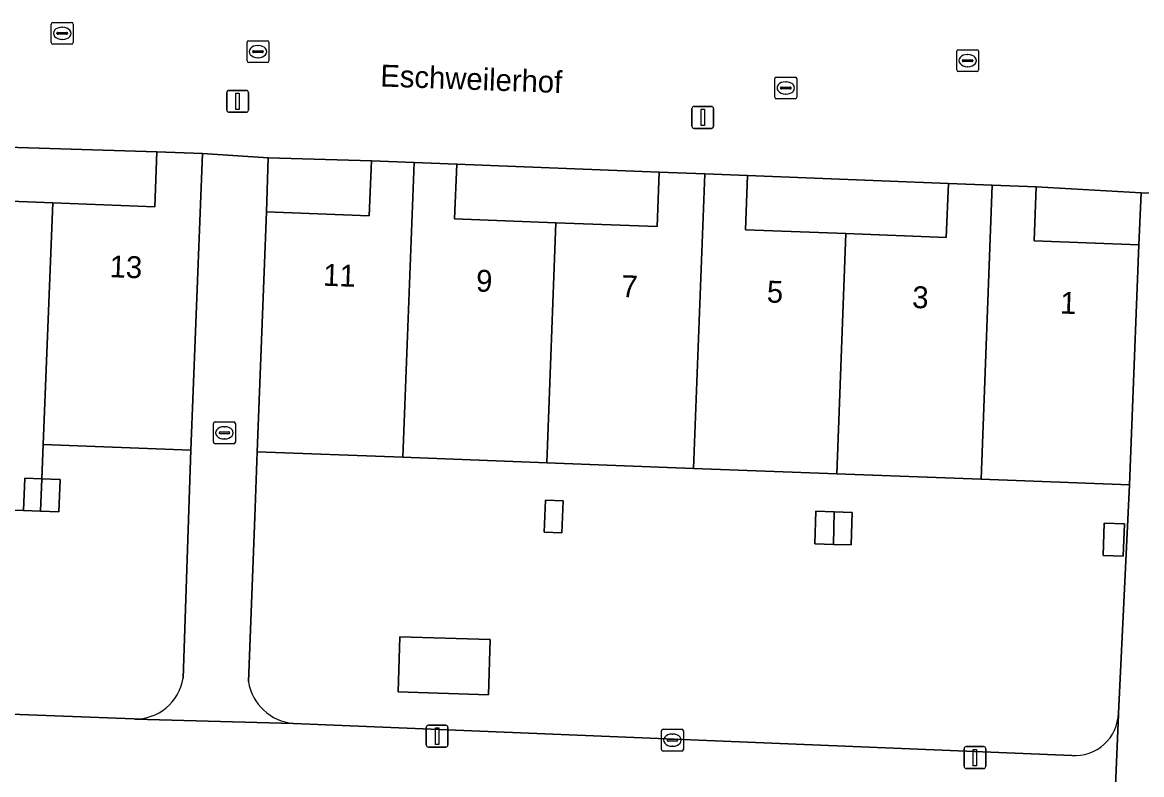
# Model space of a CAD drawing. Extents: x 160786 to 161429, y 386828 to 387485.
# Drawn here: x 161232.7 to 161283.9, y 387067.7 to 387102.1 of the extents above; entities that cross this region are included whole.
import ezdxf

# ---------------------------------------------------------------- set-up
doc = ezdxf.new("R2010")
doc.units = 0
for name, color, linetype in [('IMGEO_Erf', 7, 'Continuous'), ('IMGEO_Kolk', 7, 'Continuous'), ('IMGEO_Lichtmast', 7, 'Continuous'), ('IMGEO_Muur', 7, 'Continuous'), ('IMGEO_Openbare_ruimte_label', 7, 'Continuous'), ('IMGEO_Pand', 7, 'Continuous'), ('IMGEO_Pand_nummerreeks', 7, 'Continuous'), ('IMGEO_Rijbaan_lokaal_open', 7, 'Continuous'), ('IMGEO_Rioolput', 7, 'Continuous'), ('IMGEO_Voetpad_open', 7, 'Continuous')]:
    doc.layers.add(name, color=color, linetype=linetype)

msp = doc.modelspace()

# ---------------------------------------------------------------- linework, layer by layer
at = {"layer": 'IMGEO_Erf'}
for points in [[(161229.53, 387096.472), (161229.433, 387094.021), (161234.095, 387093.837), (161238.757, 387093.653), (161238.856, 387096.178)], [(161243.95, 387095.898), (161243.869, 387093.434), (161248.578, 387093.255), (161248.673, 387095.761)], [(161252.576, 387095.613), (161252.481, 387093.11), (161257.118, 387092.934), (161261.756, 387092.758), (161261.85, 387095.243)], [(161265.882, 387095.09), (161265.788, 387092.608), (161270.388, 387092.434), (161274.983, 387092.26), (161275.077, 387094.727)], [(161279.094, 387094.575), (161279.001, 387092.11), (161283.788, 387091.928), (161283.907, 387094.295)], [(161256.58, 387078.785), (161256.636, 387080.245), (161257.45, 387080.214), (161257.394, 387078.754)], [(161269.855, 387079.712), (161270.678, 387079.689), (161270.636, 387078.196), (161269.813, 387078.219), (161268.97, 387078.243), (161269.012, 387079.736)], [(161282.156, 387077.722), (161282.212, 387079.197), (161283.13, 387079.163), (161283.074, 387077.687)], [(161254.114, 387073.869), (161254.033, 387071.349), (161249.892, 387071.482), (161249.972, 387074.002)]]:
    msp.add_lwpolyline(points, close=True, dxfattribs=at)
for points in [[(161240.412, 387082.531), (161233.659, 387082.798), (161233.597, 387081.221), (161234.424, 387081.187), (161234.363, 387079.705), (161233.538, 387079.739), (161232.755, 387079.771), (161227.115, 387079.918)], [(161240.055, 387072.111), (161240.412, 387082.531)], [(161283.371, 387080.944), (161276.575, 387081.202), (161269.971, 387081.452), (161263.414, 387081.701), (161256.701, 387081.956), (161250.113, 387082.205), (161243.452, 387082.458), (161243.336, 387079.461), (161243.043, 387071.949)], [(161282.861, 387070.505), (161283.371, 387080.944)], [(161181.932, 387072.363), (161237.801, 387070.245)], [(161245.106, 387070.035), (161280.727, 387068.57)]]:
    msp.add_lwpolyline(points, dxfattribs=at)
for centre, radius, start, end in [((161237.887, 387072.436), 2.192, 267.7549, 351.4852), ((161245.318, 387072.333), 2.307, 189.5681, 264.7232), ((161280.858, 387070.57), 2.004, 266.2516, 358.1486)]:
    msp.add_arc(centre, radius, start, end, dxfattribs=at)
at = {"layer": 'IMGEO_Kolk'}
for p, q in [((161242.982, 387100.332), (161242.982, 387101.184)), ((161243.057, 387101.258), (161243.909, 387101.258)), ((161243.47, 387101.038), (161243.495, 387101.038)), ((161243.983, 387101.184), (161243.983, 387100.332)), ((161243.241, 387100.752), (161243.241, 387100.764)), ((161243.679, 387100.715), (161243.281, 387100.715)), ((161243.284, 387100.801), (161243.682, 387100.801)), ((161243.493, 387100.478), (161243.468, 387100.478)), ((161243.725, 387100.764), (161243.725, 387100.752)), ((161243.909, 387100.258), (161243.057, 387100.258)), ((161267.135, 387098.67), (161267.135, 387099.522)), ((161267.21, 387099.596), (161268.062, 387099.596)), ((161267.623, 387099.376), (161267.648, 387099.376)), ((161268.136, 387099.522), (161268.136, 387098.67)), ((161267.394, 387099.09), (161267.394, 387099.102)), ((161267.832, 387099.053), (161267.434, 387099.053)), ((161267.437, 387099.139), (161267.835, 387099.139)), ((161267.646, 387098.816), (161267.621, 387098.816)), ((161267.878, 387099.102), (161267.878, 387099.09)), ((161268.062, 387098.596), (161267.21, 387098.596)), ((161241.446, 387082.898), (161241.446, 387083.75)), ((161241.521, 387083.824), (161242.373, 387083.824)), ((161241.934, 387083.604), (161241.959, 387083.604)), ((161242.447, 387083.75), (161242.447, 387082.898)), ((161241.705, 387083.318), (161241.705, 387083.33)), ((161242.143, 387083.281), (161241.745, 387083.281)), ((161241.748, 387083.367), (161242.146, 387083.367)), ((161241.957, 387083.044), (161241.932, 387083.044)), ((161242.189, 387083.33), (161242.189, 387083.318)), ((161242.373, 387082.824), (161241.521, 387082.824)), ((161261.948, 387068.846), (161261.948, 387069.698)), ((161262.023, 387069.772), (161262.875, 387069.772)), ((161262.949, 387069.698), (161262.949, 387068.846)), ((161262.207, 387069.266), (161262.207, 387069.278)), ((161262.645, 387069.229), (161262.247, 387069.229)), ((161262.25, 387069.315), (161262.648, 387069.315)), ((161262.436, 387069.552), (161262.461, 387069.552)), ((161262.691, 387069.278), (161262.691, 387069.266)), ((161262.875, 387068.772), (161262.023, 387068.772)), ((161262.459, 387068.992), (161262.434, 387068.992))]:
    msp.add_line(p, q, dxfattribs=at)
for points in [[(161242.982, 387100.332), (161242.982, 387101.184)], [(161243.057, 387101.258), (161243.909, 387101.258)], [(161243.983, 387101.184), (161243.983, 387100.332)], [(161243.909, 387100.258), (161243.057, 387100.258)], [(161267.135, 387098.67), (161267.135, 387099.522)], [(161267.21, 387099.596), (161268.062, 387099.596)], [(161268.136, 387099.522), (161268.136, 387098.67)], [(161268.062, 387098.596), (161267.21, 387098.596)], [(161241.446, 387082.898), (161241.446, 387083.75)], [(161241.521, 387083.824), (161242.373, 387083.824)], [(161242.447, 387083.75), (161242.447, 387082.898)], [(161242.373, 387082.824), (161241.521, 387082.824)], [(161261.948, 387068.846), (161261.948, 387069.698)], [(161262.023, 387069.772), (161262.875, 387069.772)], [(161262.949, 387069.698), (161262.949, 387068.846)], [(161262.875, 387068.772), (161262.023, 387068.772)]]:
    msp.add_lwpolyline(points, dxfattribs=at)
for centre, radius, start, end in [((161243.059, 387101.182), 0.0765, 91.552, 178.448), ((161243.059, 387101.182), 0.0765, 91.552, 178.448), ((161243.907, 387101.182), 0.0765, 1.552, 88.448), ((161243.907, 387101.182), 0.0765, 1.552, 88.448), ((161243.059, 387100.334), 0.0765, 181.552, 268.448), ((161243.059, 387100.334), 0.0765, 181.552, 268.448), ((161243.281, 387100.761), 0.0403, 85.8775, 175.7526), ((161243.278, 387100.751), 0.0366, 178.938, 274.7102), ((161243.682, 387100.758), 0.043, 264.8664, 352.4533), ((161243.686, 387100.763), 0.0386, 1.7309, 96.639), ((161243.907, 387100.334), 0.0765, 271.552, 358.448), ((161243.907, 387100.334), 0.0765, 271.552, 358.448), ((161267.212, 387099.52), 0.0765, 91.552, 178.448), ((161267.212, 387099.52), 0.0765, 91.552, 178.448), ((161268.06, 387099.52), 0.0765, 1.552, 88.448), ((161268.06, 387099.52), 0.0765, 1.552, 88.448), ((161267.434, 387099.099), 0.0403, 85.8775, 175.7526), ((161267.431, 387099.089), 0.0366, 178.938, 274.7102), ((161267.835, 387099.096), 0.043, 264.8664, 352.4533), ((161267.839, 387099.101), 0.0386, 1.7309, 96.639), ((161267.212, 387098.672), 0.0765, 181.552, 268.448), ((161267.212, 387098.672), 0.0765, 181.552, 268.448), ((161268.06, 387098.672), 0.0765, 271.552, 358.448), ((161268.06, 387098.672), 0.0765, 271.552, 358.448), ((161241.523, 387083.748), 0.0765, 91.552, 178.448), ((161241.523, 387083.748), 0.0765, 91.552, 178.448), ((161242.371, 387083.748), 0.0765, 1.552, 88.448), ((161242.371, 387083.748), 0.0765, 1.552, 88.448), ((161241.745, 387083.327), 0.0403, 85.8775, 175.7526), ((161241.742, 387083.317), 0.0366, 178.938, 274.7102), ((161242.146, 387083.324), 0.043, 264.8664, 352.4533), ((161242.15, 387083.329), 0.0386, 1.7309, 96.639), ((161241.523, 387082.9), 0.0765, 181.552, 268.448), ((161241.523, 387082.9), 0.0765, 181.552, 268.448), ((161242.371, 387082.9), 0.0765, 271.552, 358.448), ((161242.371, 387082.9), 0.0765, 271.552, 358.448), ((161262.025, 387069.696), 0.0765, 91.552, 178.448), ((161262.025, 387069.696), 0.0765, 91.552, 178.448), ((161262.873, 387069.696), 0.0765, 1.552, 88.448), ((161262.873, 387069.696), 0.0765, 1.552, 88.448), ((161262.247, 387069.275), 0.0403, 85.8775, 175.7526), ((161262.244, 387069.265), 0.0366, 178.938, 274.7102), ((161262.648, 387069.272), 0.043, 264.8664, 352.4533), ((161262.652, 387069.277), 0.0386, 1.7309, 96.639), ((161262.025, 387068.848), 0.0765, 181.552, 268.448), ((161262.025, 387068.848), 0.0765, 181.552, 268.448), ((161262.873, 387068.848), 0.0765, 271.552, 358.448), ((161262.873, 387068.848), 0.0765, 271.552, 358.448)]:
    msp.add_arc(centre, radius, start, end, dxfattribs=at)
for centre, major_axis, ratio, start_param, end_param in [((161243.469, 387100.758), (-0.387, 0.002), 0.722429, 4.712389, 7.853982), ((161243.494, 387100.758), (-0.39, 0.002), 0.717154, 1.570796, 4.712389), ((161267.622, 387099.096), (-0.387, 0.002), 0.722429, 4.712389, 7.853982), ((161267.647, 387099.096), (-0.39, 0.002), 0.717154, 1.570796, 4.712389), ((161241.933, 387083.324), (-0.387, 0.002), 0.722429, 4.712389, 7.853982), ((161241.958, 387083.324), (-0.39, 0.002), 0.717154, 1.570796, 4.712389), ((161262.435, 387069.272), (-0.387, 0.002), 0.722429, 4.712389, 7.853982), ((161262.46, 387069.272), (-0.39, 0.002), 0.717154, 1.570796, 4.712389)]:
    msp.add_ellipse(centre, major_axis=major_axis, ratio=ratio, start_param=start_param, end_param=end_param, dxfattribs=at)
at = {"layer": 'IMGEO_Lichtmast'}
for p, q in [((161242.054, 387098.087), (161242.054, 387098.887)), ((161242.054, 387098.887), (161242.054, 387098.087)), ((161242.154, 387098.987), (161242.944, 387098.987)), ((161242.944, 387098.987), (161242.154, 387098.987)), ((161243.044, 387098.887), (161243.044, 387098.087)), ((161243.044, 387098.087), (161243.044, 387098.887)), ((161242.944, 387097.987), (161242.154, 387097.987)), ((161242.154, 387097.987), (161242.944, 387097.987)), ((161263.342, 387097.35), (161263.342, 387098.15)), ((161263.342, 387098.15), (161263.342, 387097.35)), ((161263.442, 387098.25), (161264.232, 387098.25)), ((161264.232, 387098.25), (161263.442, 387098.25)), ((161264.332, 387098.15), (161264.332, 387097.35)), ((161264.332, 387097.35), (161264.332, 387098.15)), ((161264.232, 387097.25), (161263.442, 387097.25)), ((161263.442, 387097.25), (161264.232, 387097.25)), ((161251.184, 387069.052), (161251.184, 387069.852)), ((161251.184, 387069.852), (161251.184, 387069.052)), ((161251.284, 387069.952), (161252.074, 387069.952)), ((161252.074, 387069.952), (161251.284, 387069.952)), ((161252.174, 387069.852), (161252.174, 387069.052)), ((161252.174, 387069.052), (161252.174, 387069.852)), ((161252.074, 387068.952), (161251.284, 387068.952)), ((161251.284, 387068.952), (161252.074, 387068.952)), ((161275.798, 387068.074), (161275.798, 387068.874)), ((161275.798, 387068.874), (161275.798, 387068.074)), ((161275.898, 387068.974), (161276.688, 387068.974)), ((161276.688, 387068.974), (161275.898, 387068.974)), ((161276.788, 387068.874), (161276.788, 387068.074)), ((161276.788, 387068.074), (161276.788, 387068.874)), ((161276.688, 387067.974), (161275.898, 387067.974)), ((161275.898, 387067.974), (161276.688, 387067.974))]:
    msp.add_line(p, q, dxfattribs=at)
for points in [[(161242.474, 387098.862), (161242.624, 387098.862), (161242.624, 387098.112), (161242.474, 387098.112), (161242.474, 387098.862)], [(161263.762, 387098.125), (161263.912, 387098.125), (161263.912, 387097.375), (161263.762, 387097.375), (161263.762, 387098.125)], [(161251.604, 387069.827), (161251.754, 387069.827), (161251.754, 387069.077), (161251.604, 387069.077), (161251.604, 387069.827)], [(161276.218, 387068.849), (161276.368, 387068.849), (161276.368, 387068.099), (161276.218, 387068.099), (161276.218, 387068.849)]]:
    msp.add_lwpolyline(points, dxfattribs=at)
for centre, start, end in [((161242.154, 387098.887), 90, 180), ((161242.154, 387098.887), 90, 180), ((161242.944, 387098.887), 0, 90), ((161242.944, 387098.887), 360, 90), ((161242.154, 387098.087), 180, 270), ((161242.154, 387098.087), 180, 270), ((161242.944, 387098.087), 270, 0), ((161242.944, 387098.087), 270, 0), ((161263.442, 387098.15), 90, 180), ((161263.442, 387098.15), 90, 180), ((161264.232, 387098.15), 0, 90), ((161264.232, 387098.15), 360, 90), ((161263.442, 387097.35), 180, 270), ((161263.442, 387097.35), 180, 270), ((161264.232, 387097.35), 270, 0), ((161264.232, 387097.35), 270, 0), ((161251.284, 387069.852), 90, 180), ((161251.284, 387069.852), 90, 180), ((161252.074, 387069.852), 0, 90), ((161252.074, 387069.852), 360, 90), ((161251.284, 387069.052), 180, 270), ((161251.284, 387069.052), 180, 270), ((161252.074, 387069.052), 270, 0), ((161252.074, 387069.052), 270, 0), ((161275.898, 387068.874), 90, 180), ((161275.898, 387068.874), 90, 180), ((161276.688, 387068.874), 0, 90), ((161276.688, 387068.874), 360, 90), ((161275.898, 387068.074), 180, 270), ((161275.898, 387068.074), 180, 270), ((161276.688, 387068.074), 270, 0), ((161276.688, 387068.074), 270, 0)]:
    msp.add_arc(centre, 0.1, start, end, dxfattribs=at)
at = {"layer": 'IMGEO_Muur'}
for points in [[(161240.412, 387082.531), (161240.055, 387072.111)], [(161243.452, 387082.458), (161243.336, 387079.461)], [(161283.371, 387080.944), (161282.861, 387070.505)]]:
    msp.add_lwpolyline(points, dxfattribs=at)
at = {"layer": 'IMGEO_Pand'}
for points in [[(161234.095, 387093.837), (161229.433, 387094.021), (161229.53, 387096.472), (161227.582, 387096.549), (161227.049, 387083.059), (161227.21, 387083.059), (161227.115, 387079.918), (161232.755, 387079.771), (161232.817, 387081.253), (161233.597, 387081.221), (161233.659, 387082.798)], [(161238.856, 387096.178), (161238.757, 387093.653), (161234.095, 387093.837), (161233.659, 387082.798), (161240.412, 387082.531), (161240.948, 387096.095)], [(161248.673, 387095.761), (161248.578, 387093.255), (161243.869, 387093.434), (161243.452, 387082.458), (161250.113, 387082.205), (161250.625, 387095.687)], [(161250.625, 387095.687), (161250.113, 387082.205), (161256.701, 387081.956), (161257.118, 387092.934), (161252.481, 387093.11), (161252.576, 387095.613)], [(161261.85, 387095.243), (161261.756, 387092.758), (161257.118, 387092.934), (161256.701, 387081.956), (161263.414, 387081.701), (161263.925, 387095.164)], [(161263.925, 387095.164), (161263.414, 387081.701), (161269.971, 387081.452), (161270.388, 387092.434), (161265.788, 387092.608), (161265.882, 387095.09)], [(161275.077, 387094.727), (161274.983, 387092.26), (161270.388, 387092.434), (161269.971, 387081.452), (161276.575, 387081.202), (161277.085, 387094.651)], [(161277.085, 387094.651), (161276.575, 387081.202), (161283.371, 387080.944), (161283.788, 387091.928), (161279.001, 387092.11), (161279.094, 387094.575)], [(161233.597, 387081.221), (161232.817, 387081.253), (161232.755, 387079.771), (161233.538, 387079.739)], [(161233.538, 387079.739), (161234.363, 387079.705), (161234.424, 387081.187), (161233.597, 387081.221)], [(161256.58, 387078.785), (161257.394, 387078.754), (161257.45, 387080.214), (161256.636, 387080.245)], [(161269.855, 387079.712), (161269.012, 387079.736), (161268.97, 387078.243), (161269.813, 387078.219)], [(161269.855, 387079.712), (161269.813, 387078.219), (161270.636, 387078.196), (161270.678, 387079.689)], [(161282.156, 387077.722), (161283.074, 387077.687), (161283.13, 387079.163), (161282.212, 387079.197)], [(161254.114, 387073.869), (161249.972, 387074.002), (161249.892, 387071.482), (161254.033, 387071.349)]]:
    msp.add_lwpolyline(points, close=True, dxfattribs=at)
at = {"layer": 'IMGEO_Rijbaan_lokaal_open'}
msp.add_lwpolyline([(161229.53, 387096.472), (161238.856, 387096.178), (161240.948, 387096.095), (161243.95, 387095.898), (161248.673, 387095.761), (161250.625, 387095.687), (161252.576, 387095.613), (161261.85, 387095.243), (161263.925, 387095.164), (161265.882, 387095.09), (161275.077, 387094.727), (161277.085, 387094.651), (161279.094, 387094.575), (161283.907, 387094.295), (161287.94, 387094.134)], dxfattribs=at)
at = {"layer": 'IMGEO_Rioolput'}
for p, q in [((161234.025, 387101.168), (161234.025, 387102.02)), ((161234.1, 387102.094), (161234.952, 387102.094)), ((161234.513, 387101.874), (161234.538, 387101.874)), ((161235.026, 387102.02), (161235.026, 387101.168)), ((161234.284, 387101.588), (161234.284, 387101.6)), ((161234.722, 387101.551), (161234.324, 387101.551)), ((161234.327, 387101.637), (161234.725, 387101.637)), ((161234.768, 387101.6), (161234.768, 387101.588)), ((161234.952, 387101.094), (161234.1, 387101.094)), ((161234.536, 387101.314), (161234.511, 387101.314)), ((161275.534, 387100.847), (161276.386, 387100.847)), ((161275.459, 387099.921), (161275.459, 387100.773)), ((161275.718, 387100.341), (161275.718, 387100.353)), ((161275.761, 387100.39), (161276.159, 387100.39)), ((161275.947, 387100.627), (161275.972, 387100.627)), ((161276.202, 387100.353), (161276.202, 387100.341)), ((161276.46, 387100.773), (161276.46, 387099.921)), ((161276.386, 387099.847), (161275.534, 387099.847)), ((161276.156, 387100.304), (161275.758, 387100.304)), ((161275.97, 387100.067), (161275.945, 387100.067))]:
    msp.add_line(p, q, dxfattribs=at)
for points in [[(161234.025, 387101.168), (161234.025, 387102.02)], [(161234.1, 387102.094), (161234.952, 387102.094)], [(161235.026, 387102.02), (161235.026, 387101.168)], [(161234.952, 387101.094), (161234.1, 387101.094)], [(161275.534, 387100.847), (161276.386, 387100.847)], [(161275.459, 387099.921), (161275.459, 387100.773)], [(161276.46, 387100.773), (161276.46, 387099.921)], [(161276.386, 387099.847), (161275.534, 387099.847)]]:
    msp.add_lwpolyline(points, dxfattribs=at)
for centre, radius, start, end in [((161234.102, 387102.018), 0.0765, 91.552, 178.448), ((161234.102, 387102.018), 0.0765, 91.552, 178.448), ((161234.95, 387102.018), 0.0765, 1.552, 88.448), ((161234.95, 387102.018), 0.0765, 1.552, 88.448), ((161234.324, 387101.597), 0.0403, 85.8775, 175.7526), ((161234.321, 387101.587), 0.0366, 178.938, 274.7102), ((161234.725, 387101.594), 0.043, 264.8664, 352.4533), ((161234.729, 387101.599), 0.0386, 1.7309, 96.639), ((161234.102, 387101.17), 0.0765, 181.552, 268.448), ((161234.102, 387101.17), 0.0765, 181.552, 268.448), ((161234.95, 387101.17), 0.0765, 271.552, 358.448), ((161234.95, 387101.17), 0.0765, 271.552, 358.448), ((161275.536, 387100.771), 0.0765, 91.552, 178.448), ((161275.536, 387100.771), 0.0765, 91.552, 178.448), ((161276.384, 387100.771), 0.0765, 1.552, 88.448), ((161276.384, 387100.771), 0.0765, 1.552, 88.448), ((161275.758, 387100.35), 0.0403, 85.8775, 175.7526), ((161275.755, 387100.34), 0.0366, 178.938, 274.7102), ((161276.159, 387100.347), 0.043, 264.8664, 352.4533), ((161276.163, 387100.352), 0.0386, 1.7309, 96.639), ((161275.536, 387099.923), 0.0765, 181.552, 268.448), ((161275.536, 387099.923), 0.0765, 181.552, 268.448), ((161276.384, 387099.923), 0.0765, 271.552, 358.448), ((161276.384, 387099.923), 0.0765, 271.552, 358.448)]:
    msp.add_arc(centre, radius, start, end, dxfattribs=at)
for centre, major_axis, ratio, start_param, end_param in [((161234.512, 387101.594), (-0.387, 0.002), 0.722429, 4.712389, 7.853982), ((161234.537, 387101.594), (-0.39, 0.002), 0.717154, 1.570796, 4.712389), ((161275.946, 387100.347), (-0.387, 0.002), 0.722429, 4.712389, 7.853982), ((161275.971, 387100.347), (-0.39, 0.002), 0.717154, 1.570796, 4.712389)]:
    msp.add_ellipse(centre, major_axis=major_axis, ratio=ratio, start_param=start_param, end_param=end_param, dxfattribs=at)
at = {"layer": 'IMGEO_Voetpad_open'}
for points in [[(161243.336, 387079.461), (161243.452, 387082.458), (161243.869, 387093.434), (161243.95, 387095.898), (161240.948, 387096.095), (161240.412, 387082.531), (161240.055, 387072.111)], [(161287.94, 387094.134), (161283.907, 387094.295), (161283.788, 387091.928), (161283.371, 387080.944), (161282.861, 387070.505), (161282.865, 387070.428), (161282.648, 387065.39)], [(161243.043, 387071.949), (161243.336, 387079.461)], [(161280.727, 387068.57), (161245.106, 387070.035), (161237.861, 387070.236), (161237.801, 387070.245), (161181.932, 387072.363), (161181.924, 387072.163), (161175.261, 387072.419), (161175.269, 387072.619), (161155.473, 387073.431)], [(161237.801, 387070.245), (161237.861, 387070.236), (161245.106, 387070.035)], [(161237.976, 387066.877), (161241.482, 387066.822), (161241.242, 387061.076), (161242.837, 387060.993), (161243.124, 387066.674), (161251.749, 387066.28), (161253.087, 387066.217), (161253.1, 387066.636), (161262.744, 387066.176), (161275.241, 387065.69), (161276.481, 387065.585), (161282.648, 387065.39), (161282.865, 387070.428), (161282.861, 387070.505)]]:
    msp.add_lwpolyline(points, dxfattribs=at)
for centre, radius, start, end in [((161237.887, 387072.436), 2.192, 267.7549, 351.4852), ((161245.318, 387072.333), 2.307, 189.5681, 264.7232), ((161280.858, 387070.57), 2.004, 266.2516, 358.1486)]:
    msp.add_arc(centre, radius, start, end, dxfattribs=at)

# ---------------------------------------------------------------- texts
at = {"layer": 'IMGEO_Openbare_ruimte_label'}
msp.add_text('Eschweilerhof', height=1, rotation=357.8789, dxfattribs=at).set_placement((161249.069, 387099.168))
at = {"layer": 'IMGEO_Pand_nummerreeks'}
for s, rotation, p in [('13', 357.8441, (161236.679, 387090.445)), ('11', 357.8395, (161246.451, 387090.055)), ('9', 357.8395, (161253.449, 387089.791)), ('7', 357.8395, (161260.103, 387089.54)), ('5', 357.8395, (161266.756, 387089.289)), ('3', 357.8395, (161273.409, 387089.038)), ('1', 357.8395, (161280.176, 387088.783))]:
    msp.add_text(s, height=1, rotation=rotation, dxfattribs=at).set_placement(p)

doc.saveas('drawing.dxf')
